(* Logix 5000 project; controller Electronic_Displays vendor 1 type 14 code 65 rev 17.4; software revision 17.01; part 4 of 9 *)
(* tags used below, declared in another part *)
   Address : STRING;   // "00" = all signs "01" = address 01 "02" = address 02 etc...(see protocol)
   CommandCode : STRING;   // "A" = text "B" = variable "C" = special "D" = text,norestart etc...(see protocol)
   FileLabel : STRING;   // "A" = default etc...(see protocol)
   ENText1Message : BOOL;   // 0 = don't sent message 1 = send message
   Text1Message : STRING;   // Actual Text Message to be Written to Screen (Line 1) 4 x 1 configuration
   ENText2Message : BOOL;   // 0 = don't sent message 1 = send message
   Text2Message : STRING;   // Actual Text Message to be Written to Screen (Line 2) 4 x 1 configuration
   ENText3Message : BOOL;   // 0 = don't sent message 1 = send message
   Text3Message : STRING;   // Actual Text Message to be Written to Screen (Line 3) 4 x 1 configuration
   ENText4Message : BOOL;   // 0 = don't sent message 1 = send message
   Text4Message : STRING;   // Actual Text Message to be Written to Screen (Line 4) 4 x 1 configuration
   ENTextFormats : BOOL;   // 0 = no additional text formatting 1 = enable text formatting
   TextFont : STRING;   // "0" = default "1" = SF7 "2" = SF10 "3" = SS16 "4" = SF16
   TextColor : STRING;   // "0" = Red (default) "1" = Green "2" = Yellow "3" = Rainbow1
   TextAlign : STRING;   // "M"=middle line "T"=top line "B"=bottom line "F"=fill (best for variables) "L"=left "R"=right
   TextAttribute : STRING;   // "0"=flashing off "1"=flashing on "2"=wide off "3"=wide on "4"=bold off "5"=bold on
   ENTextSpecials : BOOL;   // 0 = no additional text special formatting 1 = enable text special formatting
   TextEffect : STRING;   // "S"=scrolls "H"=hold "F"=flash "A"=slide up "B"=slide down "C"=slide left "D"=slide right "a"=roll up "b"=roll down "c"=
   TextSpeed : STRING;   // 1 - 8 "3" = Default (see protocol)
   TextPause : STRING;   // 00 - 99 "02" = Default (see protocol) [must be two digits] if not will not work!
   ENVariable1Message : BOOL;   // 0 = don't sent embedded variable 1 = send embedded variable
   Variable1Name : STRING;   // Name of variable Default is = U
   ENVariable2Message : BOOL;   // 0 = don't sent embedded variable 1 = send embedded variable
   Variable2Name : STRING;   // Name of variable Default is = V
   ENVariable3Message : BOOL;   // 0 = don't sent embedded variable 1 = send embedded variable
   Variable3Name : STRING;   // Name of variable Default is = W
   ENVariable4Message : BOOL;   // 0 = don't sent embedded variable 1 = send embedded variable
   Variable4Name : STRING;   // Name of variable Default is = X
   ENVariableFormats : BOOL;   // 0 = no additional text formatting 1 = enable text formatting
   VariableFont : STRING;   // "0" = default "1" = SF7 "2" = SF10 "3" = SS16 "4" = SF16 etc...(see protocol)
   VariableColor : STRING;   // "0" = Red (default) "1" = Green "2" = Yellow "3" = Rainbow1
   VariableAttribute : STRING;   // "0"=flashing off "1"=flashing on "2"=wide off "3"=wide on "4"=bold off "5"=bold on
   EN : BOOL;   // Instruction Interface Enable Bit
   DN : BOOL;   // Instruction Interface Done Bit
   IP : BOOL;   // Instruction Interface InProcess Bit
   ER : BOOL;   // Instruction Interface Error Bit
   Packet1Sent : STRING;   // The actual packet sent to the sign (Packet1)
   Packet2Sent : STRING;   // The actual packet sent to the sign (Packet2)
   Packet3Sent : STRING;   // The actual packet sent to the sign (Packet3)
   Packet4Sent : STRING;   // The actual packet sent to the sign (Packet4)
   Packet5Sent : STRING;   // The actual packet sent to the sign (Packet5)
   Packet6Sent : STRING;   // The actual packet sent to the sign (Packet6)
   SEQ : DINT;   // Sequence Number
   OktoCycle : BOOL;   // Ok to Cycle
   InCycle : BOOL;   // Incycle
   Error : BOOL;   // Error
   Enabled : BOOL;   // Enable ON Bit
   Done : BOOL;   // Done
   Disabled : BOOL;   // Disabled OFF Bit
   SignTextMessage1 : STRING;
   SignColor : STRING;
   SignFont : STRING;
   SignFileLabel : STRING;
   SignCommandCode : STRING;
   SignSOH : STRING;   // DO NOT EDIT = ^A
   SignAddress : STRING;
   SignSTX : STRING;   // DO NOT EDIT = ^B
   Packet : STRING[7];   // Packet Array to send to sign
   SignFontCommand : STRING;   // DO NOT EDIT = ^F
   SignColorCommand : STRING;   // DO NOT EDIT = ^O
   SignAlignCommand : STRING;   // DO NOT EDIT = ^G
   SignAlign : STRING;
   SignSpeedCommand : STRING;   // DO NOT EDIT = ^I
   SignSpeed : STRING;
   SignEffectCommand : STRING;   // DO NOT EDIT = ^E
   SignEffect : STRING;
   SignPauseCommand : STRING;   // DO NOT EDIT = ^J
   SignPause : STRING;
   SignTextMessage4 : STRING;
   SignTextMessage3 : STRING;
   SignTextMessage2 : STRING;
   SignNextLine : STRING;   // DO NOT EDIT = ^M
   SignNULL : STRING;
   SignVariableFont : STRING;
   SignVariableColor : STRING;
   SignVariable4 : STRING;
   SignVariable3 : STRING;
   SignVariable2 : STRING;
   SignVariable1 : STRING;
   SignVariableCommand : STRING;   // DO NOT EDIT = ^N
   Select : DINT;   // Packet Array Select
   TotalPacketCount : DINT[7];   // Total Character Count
   PacketMax : DINT;   // Max Packet Count
   SignMode2Command : STRING;   // DO NOT EDIT = H (make it hold)
   SignAttributeCommand : STRING;   // DO NOT EDIT = ^H
   SignAttribute : STRING;
   SignVariableAttribute : STRING;
   ENABLE : DINT;
(* SendSignMessage, continued *)

ROUTINE Logic   (* ladder *)
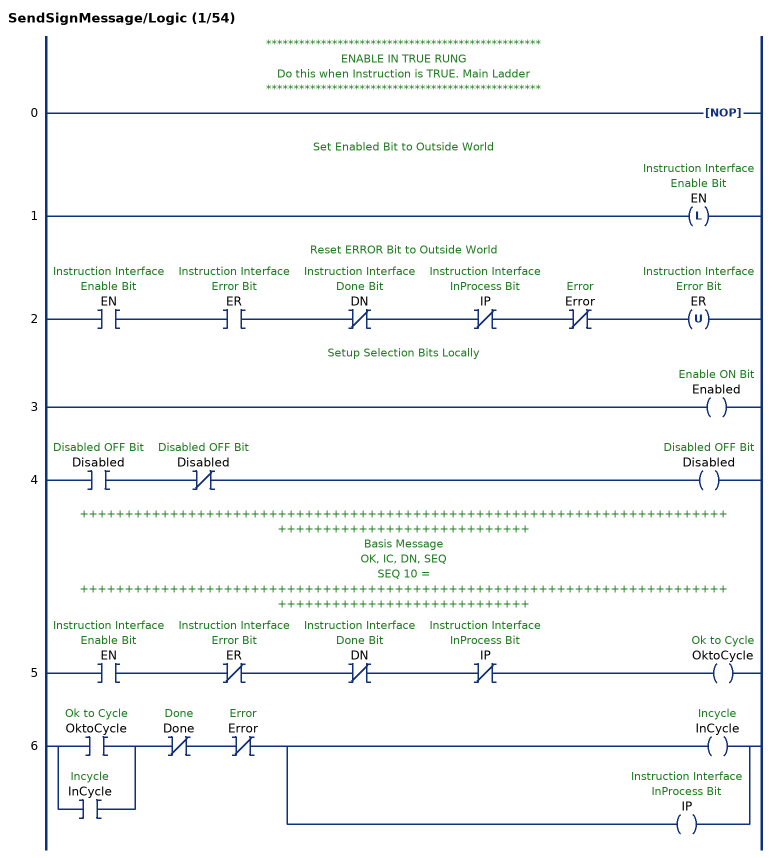
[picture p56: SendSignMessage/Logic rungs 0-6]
   // **************************************************
   // ENABLE IN TRUE RUNG
   // Do this when Instruction is TRUE. Main Ladder
   // **************************************************
   0: NOP();
   // Set Enabled Bit to Outside World
   1: OTL(EN);
   // Reset ERROR Bit to Outside World
   2: XIC(EN)XIC(ER)XIO(DN)XIO(IP)XIO(Error)OTU(ER);
   // Setup Selection Bits Locally
   3: OTE(Enabled);
   4: XIC(Disabled)XIO(Disabled)OTE(Disabled);
   // ++++++++++++++++++++++++++++++++++++++++++++++++++++++++++++++++++++++++++++++++++++++++++++++++++++
   // Basis Message
   // OK, IC, DN, SEQ
   // SEQ 10 =
   // ++++++++++++++++++++++++++++++++++++++++++++++++++++++++++++++++++++++++++++++++++++++++++++++++++++
   5: XIC(EN)XIO(ER)XIO(DN)XIO(IP)OTE(OktoCycle);
   6: [XIC(OktoCycle) ,XIC(InCycle) ]XIO(Done)XIO(Error)[OTE(InCycle) ,OTE(IP) ];
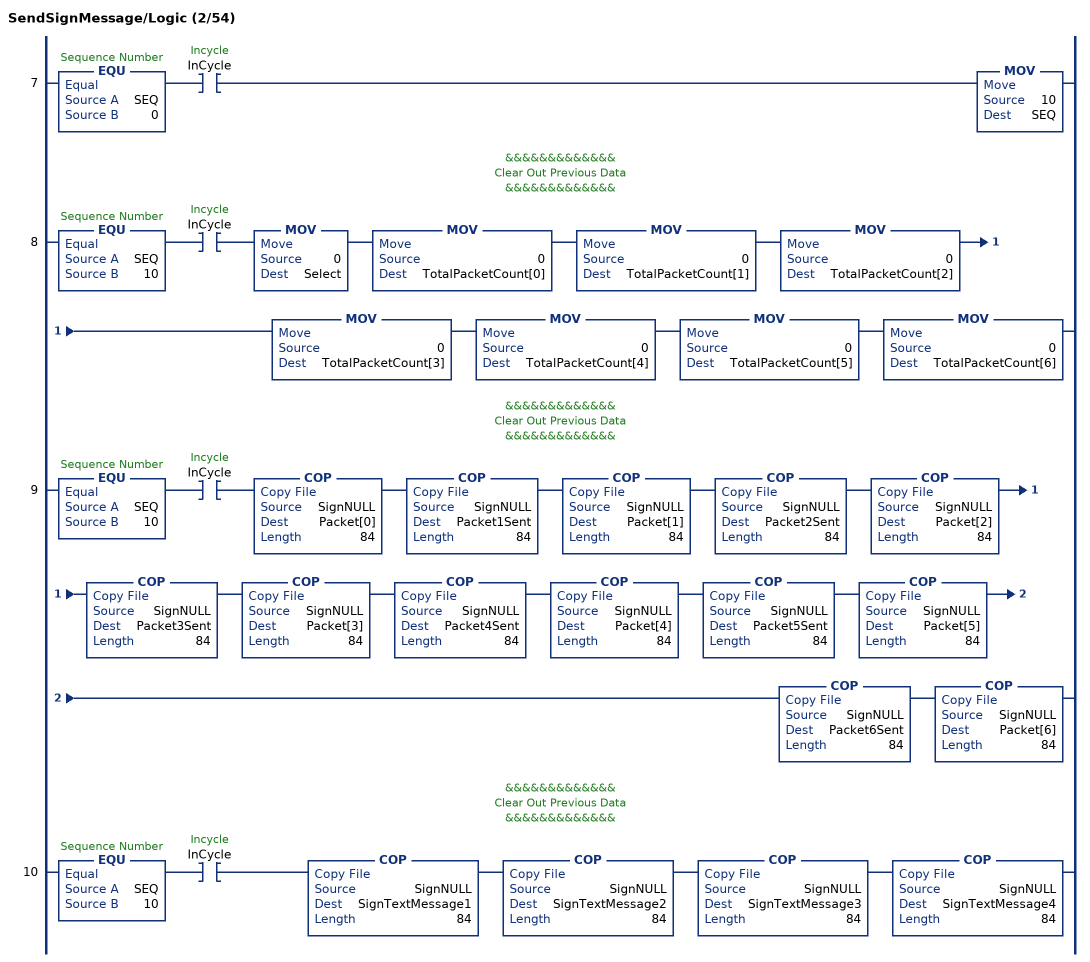
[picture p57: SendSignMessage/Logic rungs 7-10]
   7: EQU(SEQ,0)XIC(InCycle)MOV(10,SEQ);
   // &&&&&&&&&&&&&
   // Clear Out Previous Data
   // &&&&&&&&&&&&&
   8: EQU(SEQ,10)XIC(InCycle)MOV(0,Select)MOV(0,TotalPacketCount[0])MOV(0,TotalPacketCount[1])MOV(0,TotalPacketCount[2])MOV(0,TotalPacketCount[3])MOV(0,TotalPacketCount[4])MOV(0,TotalPacketCount[5])MOV(0,TotalPacketCount[6]);
   // &&&&&&&&&&&&&
   // Clear Out Previous Data
   // &&&&&&&&&&&&&
   9: EQU(SEQ,10)XIC(InCycle)COP(SignNULL,Packet[0],84)COP(SignNULL,Packet1Sent,84)COP(SignNULL,Packet[1],84)COP(SignNULL,Packet2Sent,84)COP(SignNULL,Packet[2],84)COP(SignNULL,Packet3Sent,84)COP(SignNULL,Packet[3],84)COP(SignNULL,Packet4Sent,84)COP(SignNULL,Packet[4],84)COP(SignNULL,Packet5Sent,84)COP(SignNULL,Packet[5],84)COP(SignNULL,Packet6Sent,84)COP(SignNULL,Packet[6],84);
   // &&&&&&&&&&&&&
   // Clear Out Previous Data
   // &&&&&&&&&&&&&
   10: EQU(SEQ,10)XIC(InCycle)COP(SignNULL,SignTextMessage1,84)COP(SignNULL,SignTextMessage2,84)COP(SignNULL,SignTextMessage3,84)COP(SignNULL,SignTextMessage4,84);
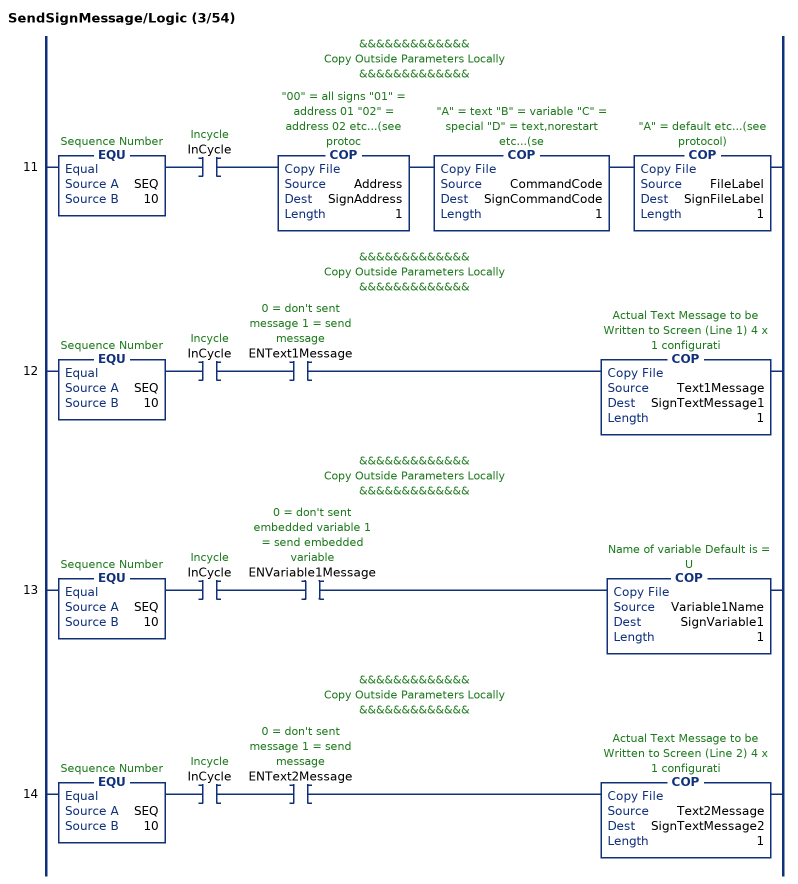
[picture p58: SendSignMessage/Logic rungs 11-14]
   // &&&&&&&&&&&&&
   // Copy Outside Parameters Locally
   // &&&&&&&&&&&&&
   11: EQU(SEQ,10)XIC(InCycle)COP(Address,SignAddress,1)COP(CommandCode,SignCommandCode,1)COP(FileLabel,SignFileLabel,1);
   // &&&&&&&&&&&&&
   // Copy Outside Parameters Locally
   // &&&&&&&&&&&&&
   12: EQU(SEQ,10)XIC(InCycle)XIC(ENText1Message)COP(Text1Message,SignTextMessage1,1);
   // &&&&&&&&&&&&&
   // Copy Outside Parameters Locally
   // &&&&&&&&&&&&&
   13: EQU(SEQ,10)XIC(InCycle)XIC(ENVariable1Message)COP(Variable1Name,SignVariable1,1);
   // &&&&&&&&&&&&&
   // Copy Outside Parameters Locally
   // &&&&&&&&&&&&&
   14: EQU(SEQ,10)XIC(InCycle)XIC(ENText2Message)COP(Text2Message,SignTextMessage2,1);
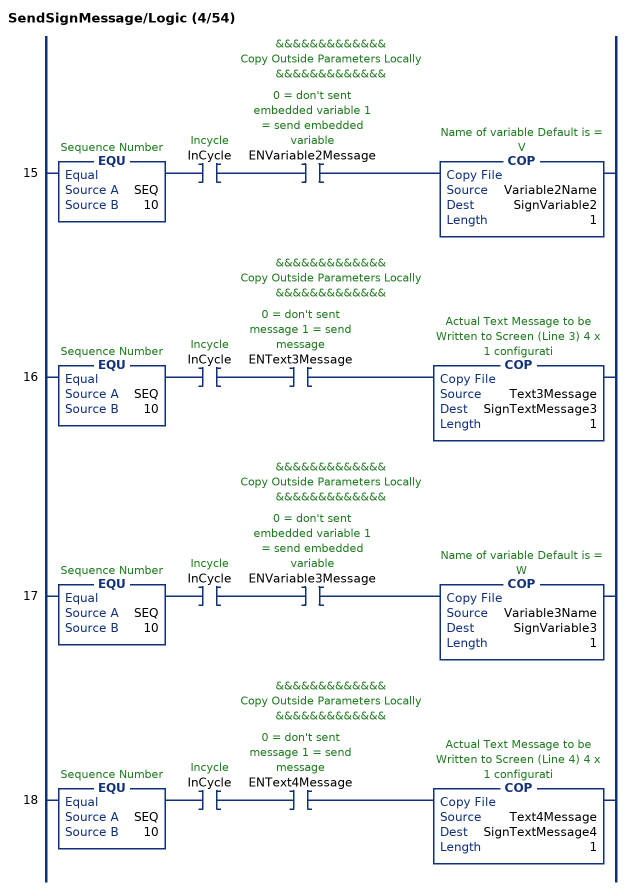
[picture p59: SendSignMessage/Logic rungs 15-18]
   // &&&&&&&&&&&&&
   // Copy Outside Parameters Locally
   // &&&&&&&&&&&&&
   15: EQU(SEQ,10)XIC(InCycle)XIC(ENVariable2Message)COP(Variable2Name,SignVariable2,1);
   // &&&&&&&&&&&&&
   // Copy Outside Parameters Locally
   // &&&&&&&&&&&&&
   16: EQU(SEQ,10)XIC(InCycle)XIC(ENText3Message)COP(Text3Message,SignTextMessage3,1);
   // &&&&&&&&&&&&&
   // Copy Outside Parameters Locally
   // &&&&&&&&&&&&&
   17: EQU(SEQ,10)XIC(InCycle)XIC(ENVariable3Message)COP(Variable3Name,SignVariable3,1);
   // &&&&&&&&&&&&&
   // Copy Outside Parameters Locally
   // &&&&&&&&&&&&&
   18: EQU(SEQ,10)XIC(InCycle)XIC(ENText4Message)COP(Text4Message,SignTextMessage4,1);
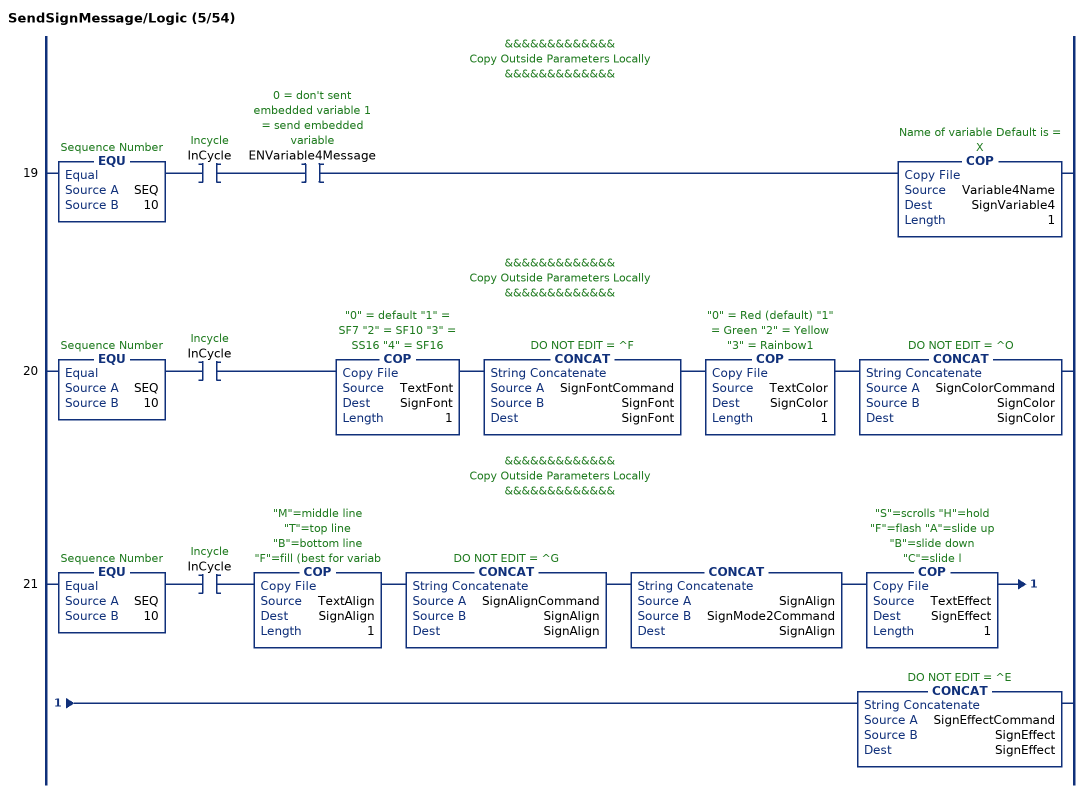
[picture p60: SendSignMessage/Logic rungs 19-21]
   // &&&&&&&&&&&&&
   // Copy Outside Parameters Locally
   // &&&&&&&&&&&&&
   19: EQU(SEQ,10)XIC(InCycle)XIC(ENVariable4Message)COP(Variable4Name,SignVariable4,1);
   // &&&&&&&&&&&&&
   // Copy Outside Parameters Locally
   // &&&&&&&&&&&&&
   20: EQU(SEQ,10)XIC(InCycle)COP(TextFont,SignFont,1)CONCAT(SignFontCommand,SignFont,SignFont)COP(TextColor,SignColor,1)CONCAT(SignColorCommand,SignColor,SignColor);
   // &&&&&&&&&&&&&
   // Copy Outside Parameters Locally
   // &&&&&&&&&&&&&
   21: EQU(SEQ,10)XIC(InCycle)COP(TextAlign,SignAlign,1)CONCAT(SignAlignCommand,SignAlign,SignAlign)CONCAT(SignAlign,SignMode2Command,SignAlign)COP(TextEffect,SignEffect,1)CONCAT(SignEffectCommand,SignEffect,SignEffect);
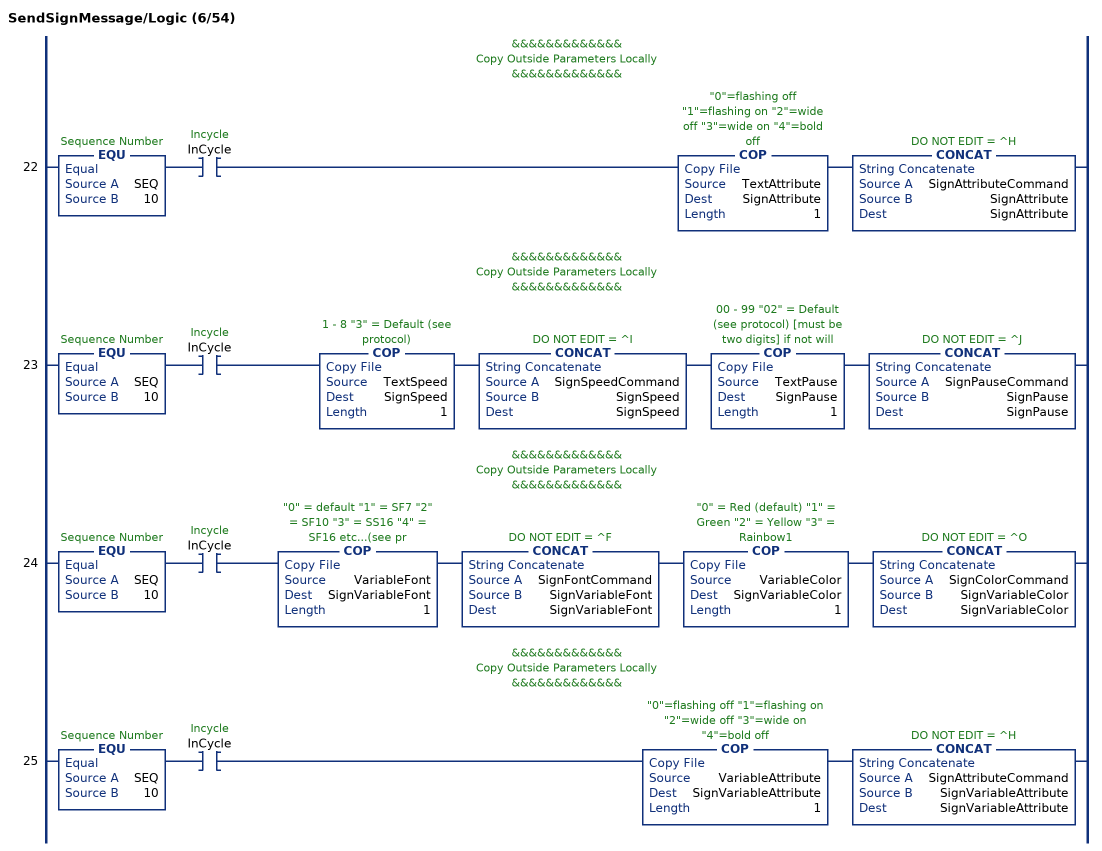
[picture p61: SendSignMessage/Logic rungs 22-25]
   // &&&&&&&&&&&&&
   // Copy Outside Parameters Locally
   // &&&&&&&&&&&&&
   22: EQU(SEQ,10)XIC(InCycle)COP(TextAttribute,SignAttribute,1)CONCAT(SignAttributeCommand,SignAttribute,SignAttribute);
   // &&&&&&&&&&&&&
   // Copy Outside Parameters Locally
   // &&&&&&&&&&&&&
   23: EQU(SEQ,10)XIC(InCycle)COP(TextSpeed,SignSpeed,1)CONCAT(SignSpeedCommand,SignSpeed,SignSpeed)COP(TextPause,SignPause,1)CONCAT(SignPauseCommand,SignPause,SignPause);
   // &&&&&&&&&&&&&
   // Copy Outside Parameters Locally
   // &&&&&&&&&&&&&
   24: EQU(SEQ,10)XIC(InCycle)COP(VariableFont,SignVariableFont,1)CONCAT(SignFontCommand,SignVariableFont,SignVariableFont)COP(VariableColor,SignVariableColor,1)CONCAT(SignColorCommand,SignVariableColor,SignVariableColor);
   // &&&&&&&&&&&&&
   // Copy Outside Parameters Locally
   // &&&&&&&&&&&&&
   25: EQU(SEQ,10)XIC(InCycle)COP(VariableAttribute,SignVariableAttribute,1)CONCAT(SignAttributeCommand,SignVariableAttribute,SignVariableAttribute);
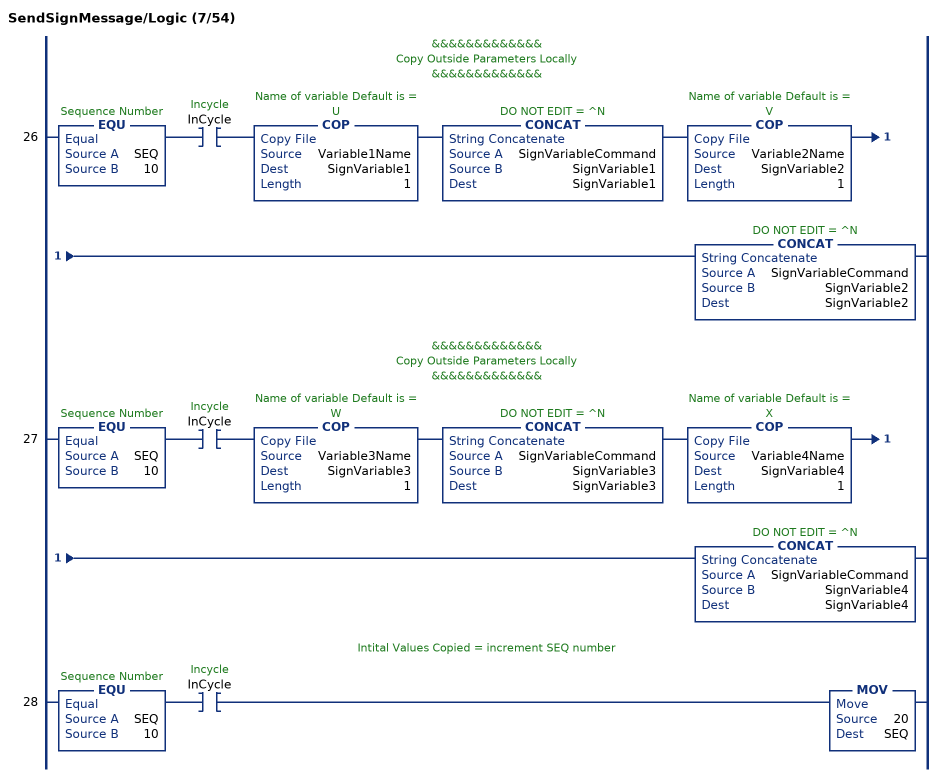
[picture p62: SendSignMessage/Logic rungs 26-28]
   // &&&&&&&&&&&&&
   // Copy Outside Parameters Locally
   // &&&&&&&&&&&&&
   26: EQU(SEQ,10)XIC(InCycle)COP(Variable1Name,SignVariable1,1)CONCAT(SignVariableCommand,SignVariable1,SignVariable1)COP(Variable2Name,SignVariable2,1)CONCAT(SignVariableCommand,SignVariable2,SignVariable2);
   // &&&&&&&&&&&&&
   // Copy Outside Parameters Locally
   // &&&&&&&&&&&&&
   27: EQU(SEQ,10)XIC(InCycle)COP(Variable3Name,SignVariable3,1)CONCAT(SignVariableCommand,SignVariable3,SignVariable3)COP(Variable4Name,SignVariable4,1)CONCAT(SignVariableCommand,SignVariable4,SignVariable4);
   // Intital Values Copied = increment SEQ number
   28: EQU(SEQ,10)XIC(InCycle)MOV(20,SEQ);
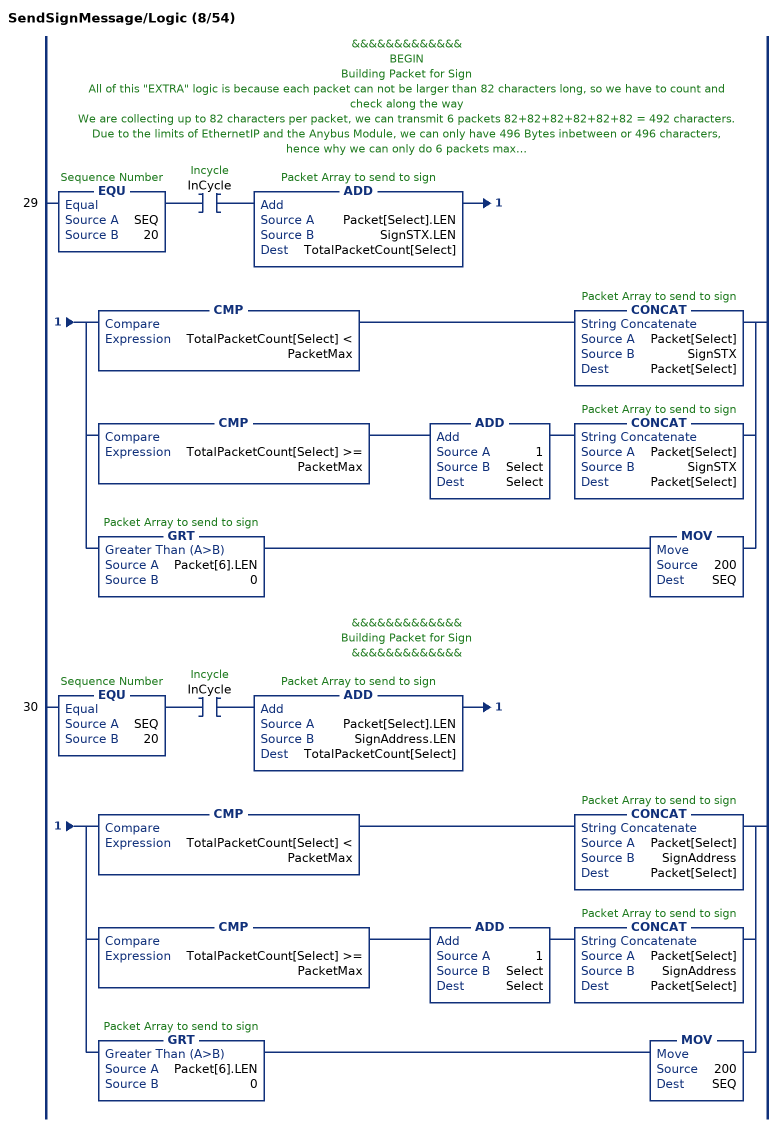
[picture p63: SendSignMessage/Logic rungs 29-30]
   // &&&&&&&&&&&&&
   // BEGIN
   // Building Packet for Sign
   // All of this "EXTRA" logic is because each packet can not be larger than 82 characters long, so we have to count and check along the way
   // We are collecting up to 82 characters per packet, we can transmit 6 packets 82+82+82+82+82+82 = 492 characters.
   // Due to the limits of EthernetIP and the Anybus Module, we can only have 496 Bytes inbetween or 496 characters, hence why we can only do 6 packets max.
   // Once we exceed this, we will fault and ERROR trap any windy typing people.
   // &&&&&&&&&&&&&
   29: EQU(SEQ,20)XIC(InCycle)ADD(Packet[Select].LEN,SignSTX.LEN,TotalPacketCount[Select])[CMP(TotalPacketCount[Select] < PacketMax) CONCAT(Packet[Select],SignSTX,Packet[Select]) ,CMP(TotalPacketCount[Select] >= PacketMax) ADD(1,Select,Select) CONCAT(Packet[Select],SignSTX,Packet[Select]) ,GRT(Packet[6].LEN,0) MOV(200,SEQ) ];
   // &&&&&&&&&&&&&
   // Building Packet for Sign
   // &&&&&&&&&&&&&
   30: EQU(SEQ,20)XIC(InCycle)ADD(Packet[Select].LEN,SignAddress.LEN,TotalPacketCount[Select])[CMP(TotalPacketCount[Select] < PacketMax) CONCAT(Packet[Select],SignAddress,Packet[Select]) ,CMP(TotalPacketCount[Select] >= PacketMax) ADD(1,Select,Select) CONCAT(Packet[Select],SignAddress,Packet[Select]) ,GRT(Packet[6].LEN,0) MOV(200,SEQ) ];
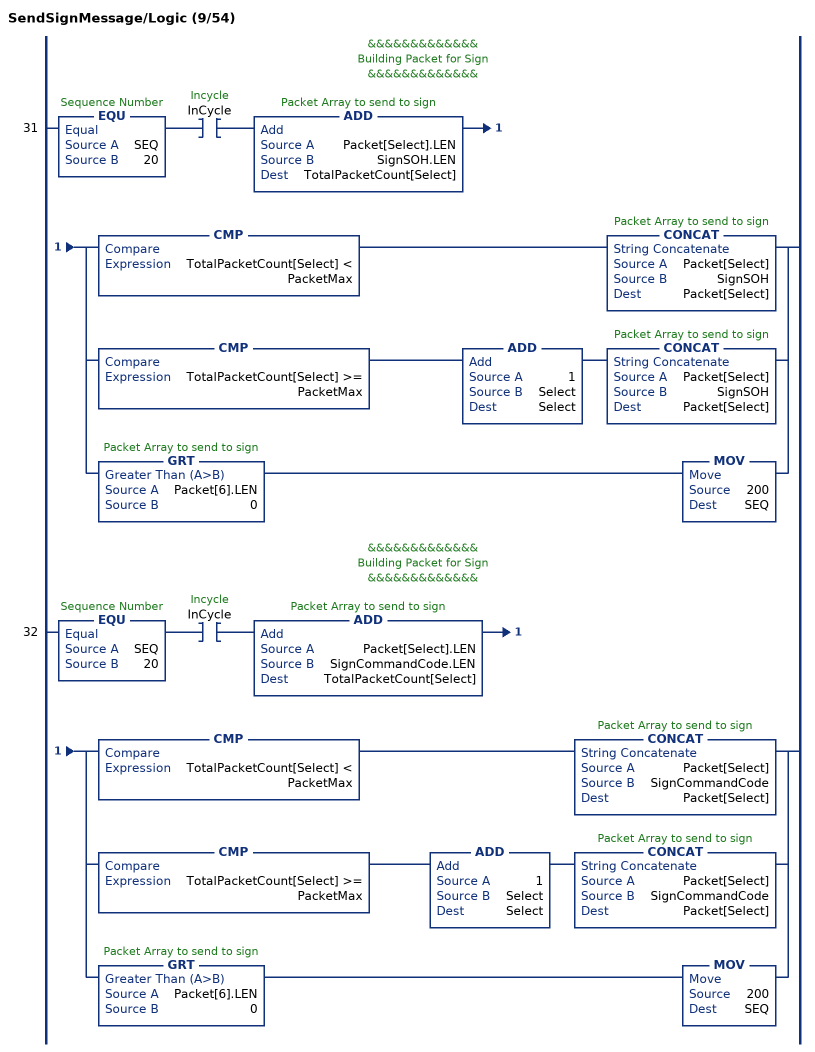
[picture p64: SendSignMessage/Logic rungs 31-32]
   // &&&&&&&&&&&&&
   // Building Packet for Sign
   // &&&&&&&&&&&&&
   31: EQU(SEQ,20)XIC(InCycle)ADD(Packet[Select].LEN,SignSOH.LEN,TotalPacketCount[Select])[CMP(TotalPacketCount[Select] < PacketMax) CONCAT(Packet[Select],SignSOH,Packet[Select]) ,CMP(TotalPacketCount[Select] >= PacketMax) ADD(1,Select,Select) CONCAT(Packet[Select],SignSOH,Packet[Select]) ,GRT(Packet[6].LEN,0) MOV(200,SEQ) ];
   // &&&&&&&&&&&&&
   // Building Packet for Sign
   // &&&&&&&&&&&&&
   32: EQU(SEQ,20)XIC(InCycle)ADD(Packet[Select].LEN,SignCommandCode.LEN,TotalPacketCount[Select])[CMP(TotalPacketCount[Select] < PacketMax) CONCAT(Packet[Select],SignCommandCode,Packet[Select]) ,CMP(TotalPacketCount[Select] >= PacketMax) ADD(1,Select,Select) CONCAT(Packet[Select],SignCommandCode,Packet[Select]) ,GRT(Packet[6].LEN,0) MOV(200,SEQ) ];
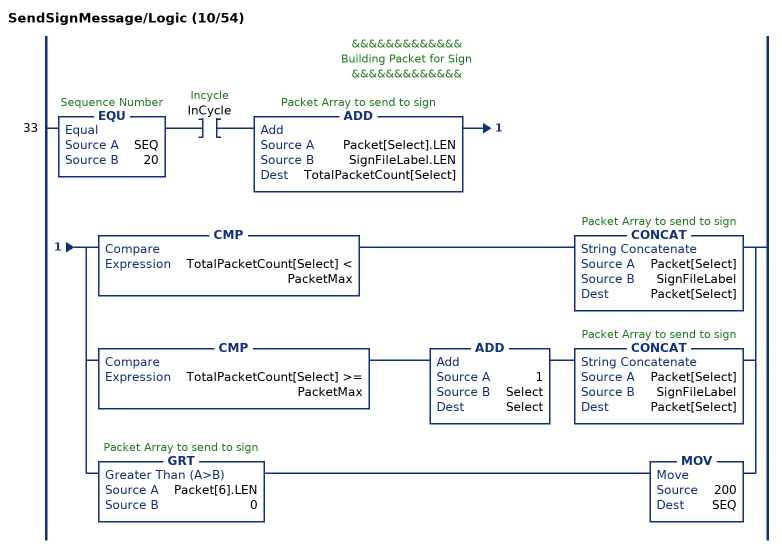
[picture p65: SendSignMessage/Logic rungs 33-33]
   // &&&&&&&&&&&&&
   // Building Packet for Sign
   // &&&&&&&&&&&&&
   33: EQU(SEQ,20)XIC(InCycle)ADD(Packet[Select].LEN,SignFileLabel.LEN,TotalPacketCount[Select])[CMP(TotalPacketCount[Select] < PacketMax) CONCAT(Packet[Select],SignFileLabel,Packet[Select]) ,CMP(TotalPacketCount[Select] >= PacketMax) ADD(1,Select,Select) CONCAT(Packet[Select],SignFileLabel,Packet[Select]) ,GRT(Packet[6].LEN,0) MOV(200,SEQ) ];
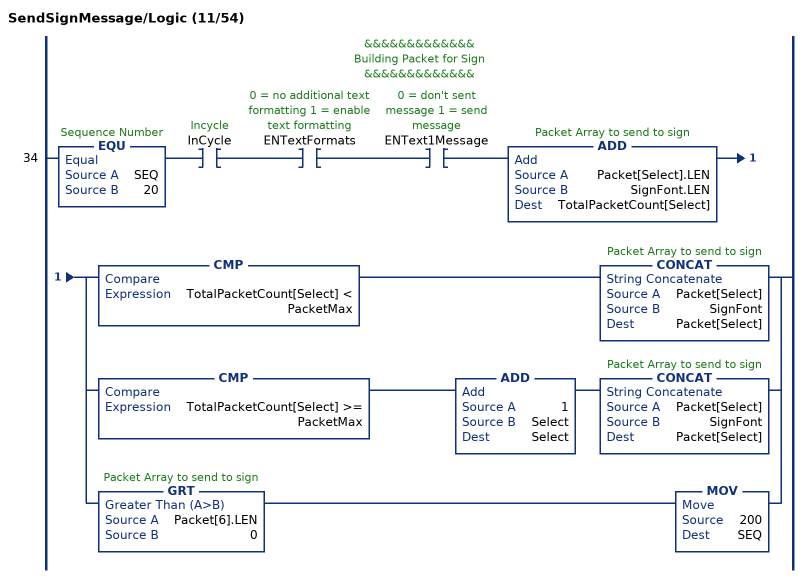
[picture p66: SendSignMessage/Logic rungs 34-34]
   // &&&&&&&&&&&&&
   // Building Packet for Sign
   // &&&&&&&&&&&&&
   34: EQU(SEQ,20)XIC(InCycle)XIC(ENTextFormats)XIC(ENText1Message)ADD(Packet[Select].LEN,SignFont.LEN,TotalPacketCount[Select])[CMP(TotalPacketCount[Select] < PacketMax) CONCAT(Packet[Select],SignFont,Packet[Select]) ,CMP(TotalPacketCount[Select] >= PacketMax) ADD(1,Select,Select) CONCAT(Packet[Select],SignFont,Packet[Select]) ,GRT(Packet[6].LEN,0) MOV(200,SEQ) ];
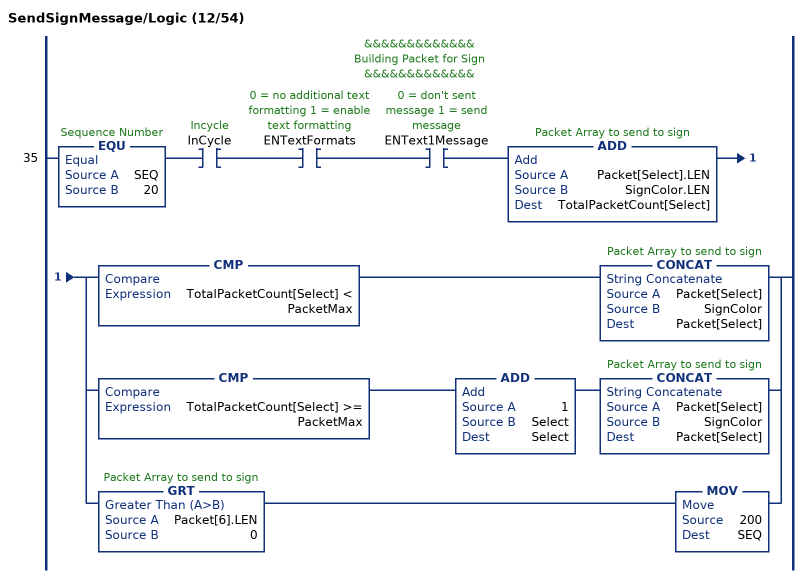
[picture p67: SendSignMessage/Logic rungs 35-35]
   // &&&&&&&&&&&&&
   // Building Packet for Sign
   // &&&&&&&&&&&&&
   35: EQU(SEQ,20)XIC(InCycle)XIC(ENTextFormats)XIC(ENText1Message)ADD(Packet[Select].LEN,SignColor.LEN,TotalPacketCount[Select])[CMP(TotalPacketCount[Select] < PacketMax) CONCAT(Packet[Select],SignColor,Packet[Select]) ,CMP(TotalPacketCount[Select] >= PacketMax) ADD(1,Select,Select) CONCAT(Packet[Select],SignColor,Packet[Select]) ,GRT(Packet[6].LEN,0) MOV(200,SEQ) ];
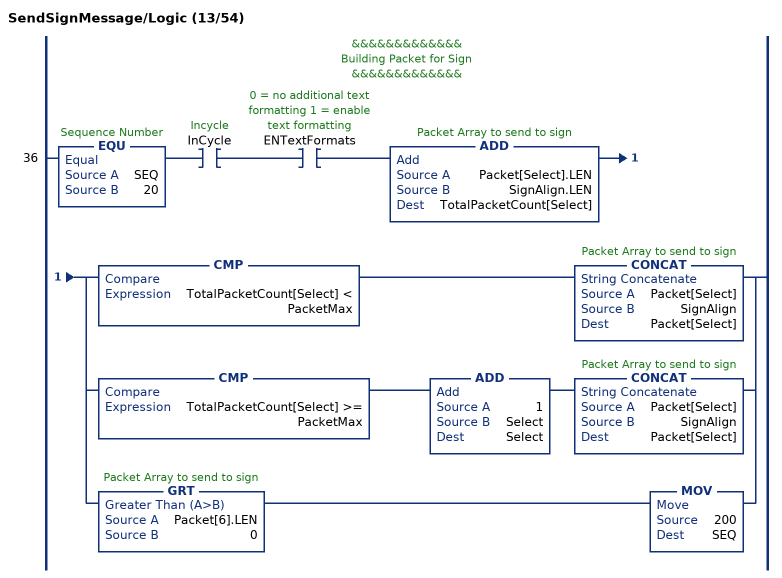
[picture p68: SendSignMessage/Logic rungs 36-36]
   // &&&&&&&&&&&&&
   // Building Packet for Sign
   // &&&&&&&&&&&&&
   36: EQU(SEQ,20)XIC(InCycle)XIC(ENTextFormats)ADD(Packet[Select].LEN,SignAlign.LEN,TotalPacketCount[Select])[CMP(TotalPacketCount[Select] < PacketMax) CONCAT(Packet[Select],SignAlign,Packet[Select]) ,CMP(TotalPacketCount[Select] >= PacketMax) ADD(1,Select,Select) CONCAT(Packet[Select],SignAlign,Packet[Select]) ,GRT(Packet[6].LEN,0) MOV(200,SEQ) ];
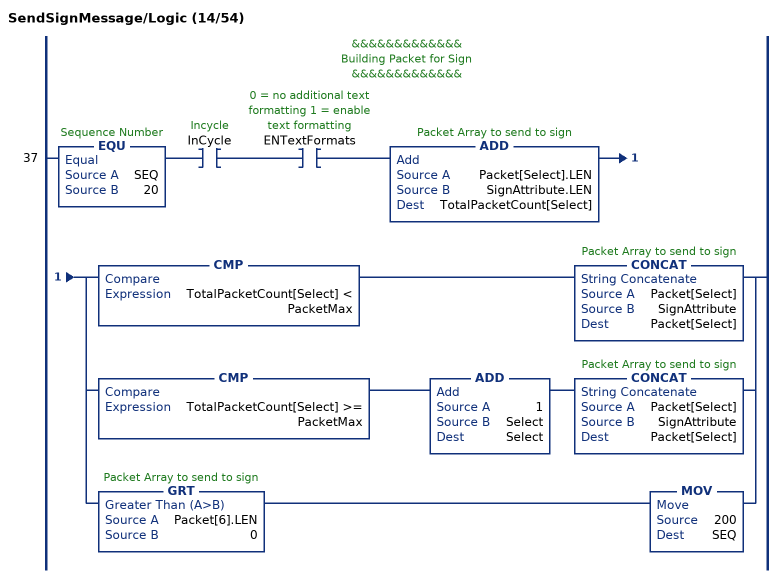
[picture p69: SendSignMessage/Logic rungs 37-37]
   // &&&&&&&&&&&&&
   // Building Packet for Sign
   // &&&&&&&&&&&&&
   37: EQU(SEQ,20)XIC(InCycle)XIC(ENTextFormats)ADD(Packet[Select].LEN,SignAttribute.LEN,TotalPacketCount[Select])[CMP(TotalPacketCount[Select] < PacketMax) CONCAT(Packet[Select],SignAttribute,Packet[Select]) ,CMP(TotalPacketCount[Select] >= PacketMax) ADD(1,Select,Select) CONCAT(Packet[Select],SignAttribute,Packet[Select]) ,GRT(Packet[6].LEN,0) MOV(200,SEQ) ];
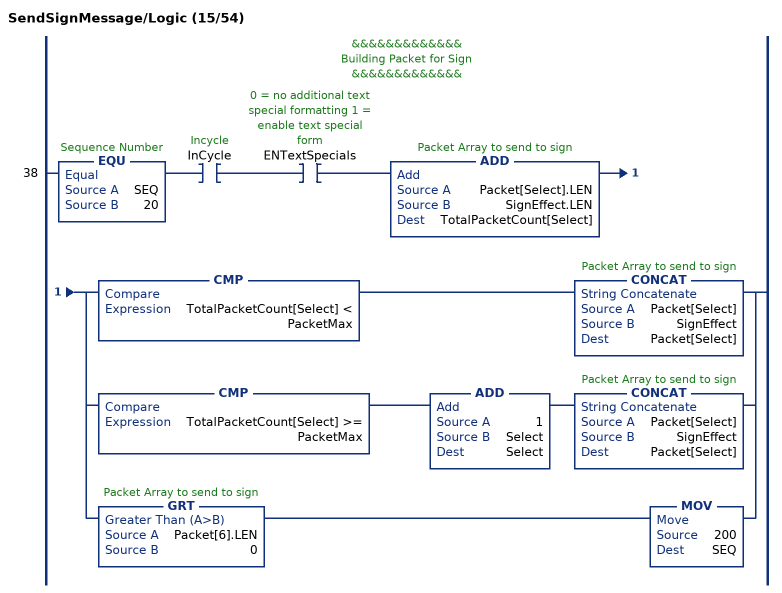
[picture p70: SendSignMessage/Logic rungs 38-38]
   // &&&&&&&&&&&&&
   // Building Packet for Sign
   // &&&&&&&&&&&&&
   38: EQU(SEQ,20)XIC(InCycle)XIC(ENTextSpecials)ADD(Packet[Select].LEN,SignEffect.LEN,TotalPacketCount[Select])[CMP(TotalPacketCount[Select] < PacketMax) CONCAT(Packet[Select],SignEffect,Packet[Select]) ,CMP(TotalPacketCount[Select] >= PacketMax) ADD(1,Select,Select) CONCAT(Packet[Select],SignEffect,Packet[Select]) ,GRT(Packet[6].LEN,0) MOV(200,SEQ) ];
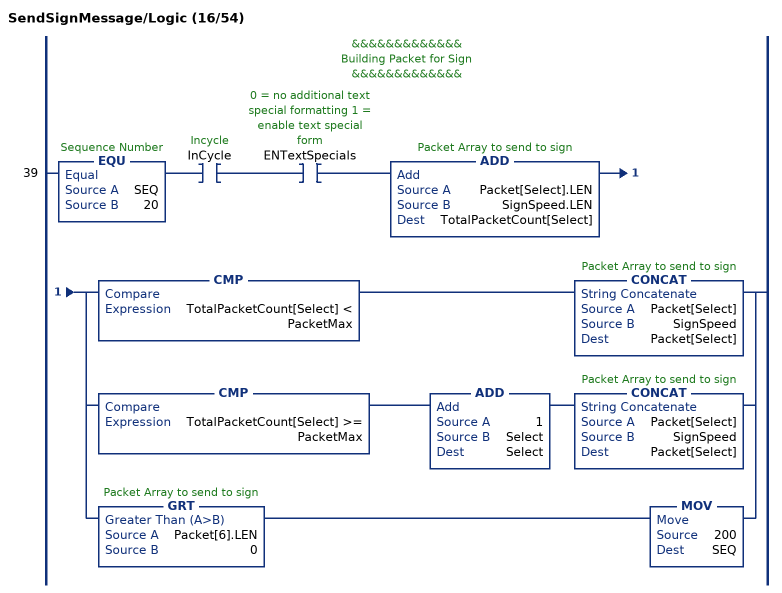
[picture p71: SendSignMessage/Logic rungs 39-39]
   // &&&&&&&&&&&&&
   // Building Packet for Sign
   // &&&&&&&&&&&&&
   39: EQU(SEQ,20)XIC(InCycle)XIC(ENTextSpecials)ADD(Packet[Select].LEN,SignSpeed.LEN,TotalPacketCount[Select])[CMP(TotalPacketCount[Select] < PacketMax) CONCAT(Packet[Select],SignSpeed,Packet[Select]) ,CMP(TotalPacketCount[Select] >= PacketMax) ADD(1,Select,Select) CONCAT(Packet[Select],SignSpeed,Packet[Select]) ,GRT(Packet[6].LEN,0) MOV(200,SEQ) ];
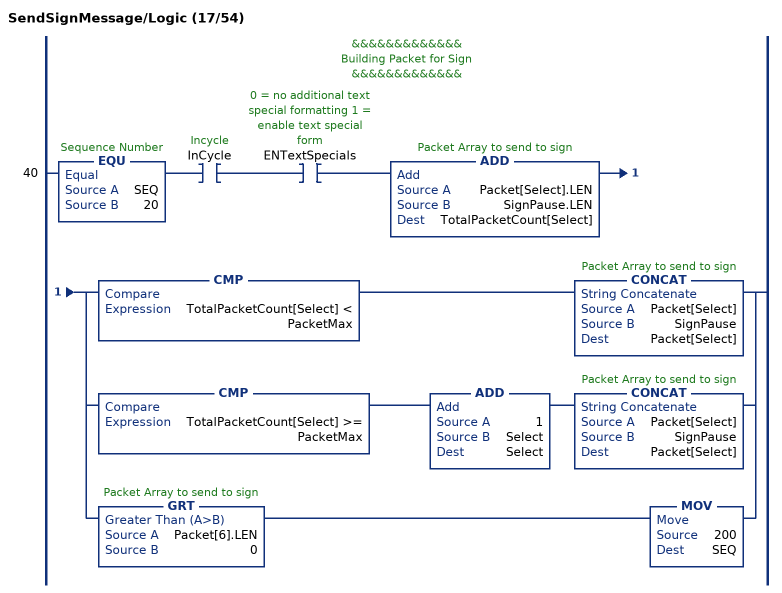
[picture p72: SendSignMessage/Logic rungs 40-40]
   // &&&&&&&&&&&&&
   // Building Packet for Sign
   // &&&&&&&&&&&&&
   40: EQU(SEQ,20)XIC(InCycle)XIC(ENTextSpecials)ADD(Packet[Select].LEN,SignPause.LEN,TotalPacketCount[Select])[CMP(TotalPacketCount[Select] < PacketMax) CONCAT(Packet[Select],SignPause,Packet[Select]) ,CMP(TotalPacketCount[Select] >= PacketMax) ADD(1,Select,Select) CONCAT(Packet[Select],SignPause,Packet[Select]) ,GRT(Packet[6].LEN,0) MOV(200,SEQ) ];
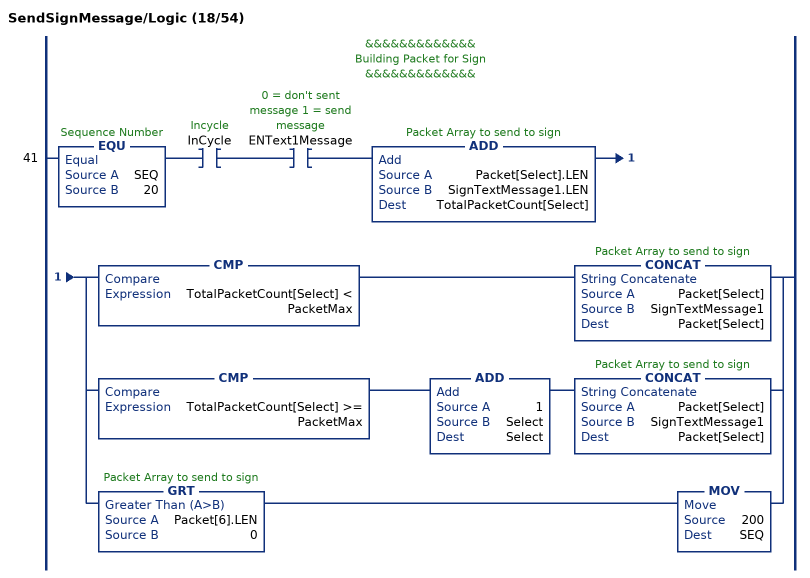
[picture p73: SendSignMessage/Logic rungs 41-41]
   // &&&&&&&&&&&&&
   // Building Packet for Sign
   // &&&&&&&&&&&&&
   41: EQU(SEQ,20)XIC(InCycle)XIC(ENText1Message)ADD(Packet[Select].LEN,SignTextMessage1.LEN,TotalPacketCount[Select])[CMP(TotalPacketCount[Select] < PacketMax) CONCAT(Packet[Select],SignTextMessage1,Packet[Select]) ,CMP(TotalPacketCount[Select] >= PacketMax) ADD(1,Select,Select) CONCAT(Packet[Select],SignTextMessage1,Packet[Select]) ,GRT(Packet[6].LEN,0) MOV(200,SEQ) ];
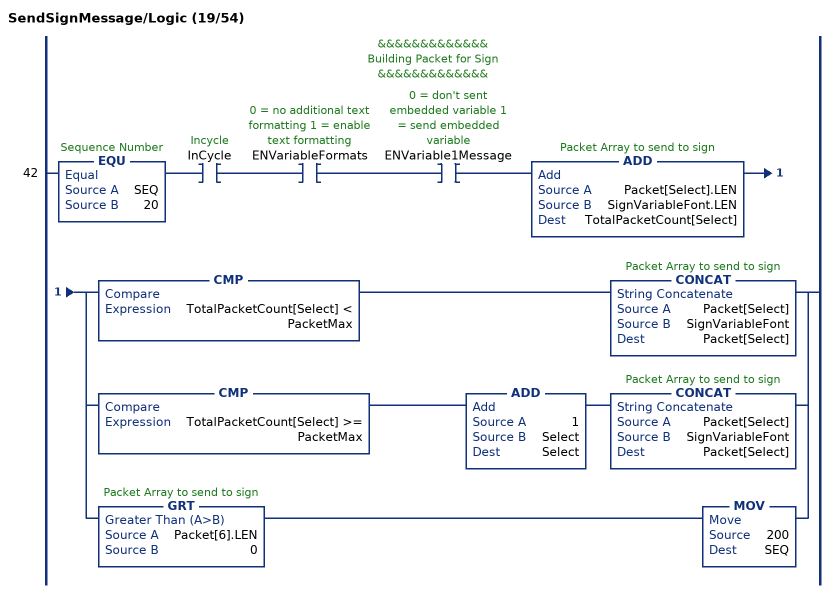
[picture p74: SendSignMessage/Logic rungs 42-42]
   // &&&&&&&&&&&&&
   // Building Packet for Sign
   // &&&&&&&&&&&&&
   42: EQU(SEQ,20)XIC(InCycle)XIC(ENVariableFormats)XIC(ENVariable1Message)ADD(Packet[Select].LEN,SignVariableFont.LEN,TotalPacketCount[Select])[CMP(TotalPacketCount[Select] < PacketMax) CONCAT(Packet[Select],SignVariableFont,Packet[Select]) ,CMP(TotalPacketCount[Select] >= PacketMax) ADD(1,Select,Select) CONCAT(Packet[Select],SignVariableFont,Packet[Select]) ,GRT(Packet[6].LEN,0) MOV(200,SEQ) ];
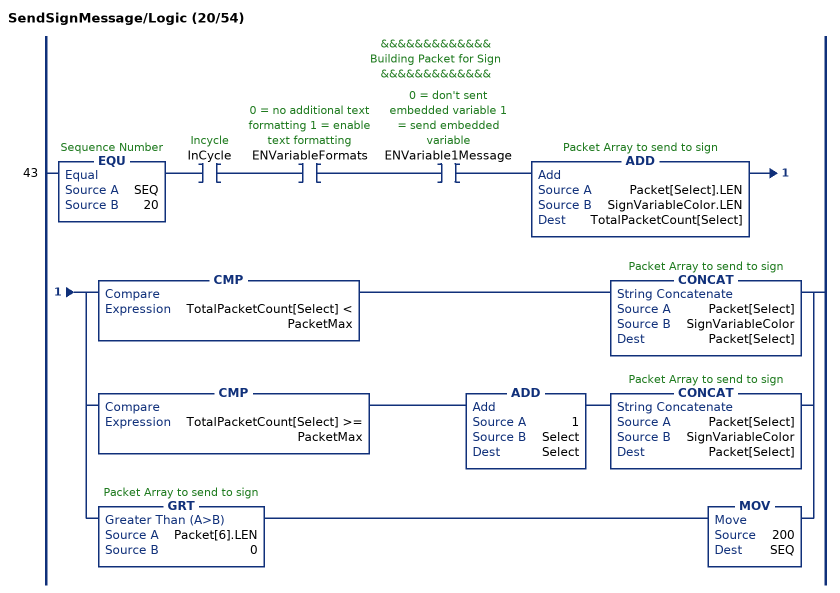
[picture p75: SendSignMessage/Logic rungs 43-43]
   // &&&&&&&&&&&&&
   // Building Packet for Sign
   // &&&&&&&&&&&&&
   43: EQU(SEQ,20)XIC(InCycle)XIC(ENVariableFormats)XIC(ENVariable1Message)ADD(Packet[Select].LEN,SignVariableColor.LEN,TotalPacketCount[Select])[CMP(TotalPacketCount[Select] < PacketMax) CONCAT(Packet[Select],SignVariableColor,Packet[Select]) ,CMP(TotalPacketCount[Select] >= PacketMax) ADD(1,Select,Select) CONCAT(Packet[Select],SignVariableColor,Packet[Select]) ,GRT(Packet[6].LEN,0) MOV(200,SEQ) ];
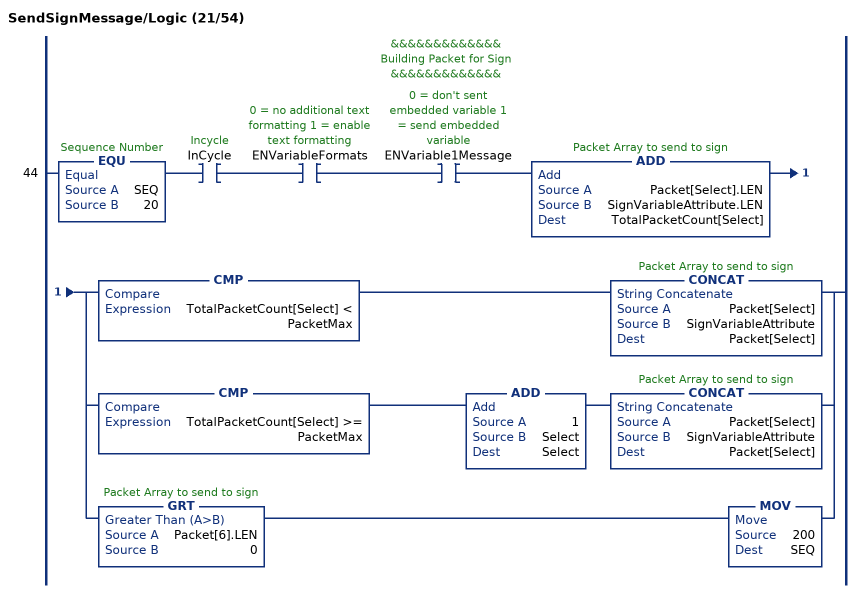
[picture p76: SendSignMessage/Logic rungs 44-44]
   // &&&&&&&&&&&&&
   // Building Packet for Sign
   // &&&&&&&&&&&&&
   44: EQU(SEQ,20)XIC(InCycle)XIC(ENVariableFormats)XIC(ENVariable1Message)ADD(Packet[Select].LEN,SignVariableAttribute.LEN,TotalPacketCount[Select])[CMP(TotalPacketCount[Select] < PacketMax) CONCAT(Packet[Select],SignVariableAttribute,Packet[Select]) ,CMP(TotalPacketCount[Select] >= PacketMax) ADD(1,Select,Select) CONCAT(Packet[Select],SignVariableAttribute,Packet[Select]) ,GRT(Packet[6].LEN,0) MOV(200,SEQ) ];
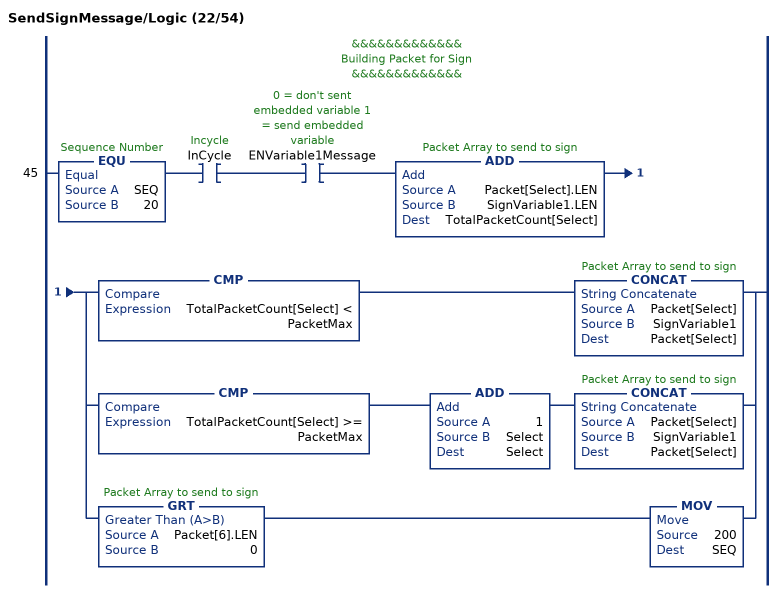
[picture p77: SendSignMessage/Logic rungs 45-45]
   // &&&&&&&&&&&&&
   // Building Packet for Sign
   // &&&&&&&&&&&&&
   45: EQU(SEQ,20)XIC(InCycle)XIC(ENVariable1Message)ADD(Packet[Select].LEN,SignVariable1.LEN,TotalPacketCount[Select])[CMP(TotalPacketCount[Select] < PacketMax) CONCAT(Packet[Select],SignVariable1,Packet[Select]) ,CMP(TotalPacketCount[Select] >= PacketMax) ADD(1,Select,Select) CONCAT(Packet[Select],SignVariable1,Packet[Select]) ,GRT(Packet[6].LEN,0) MOV(200,SEQ) ];
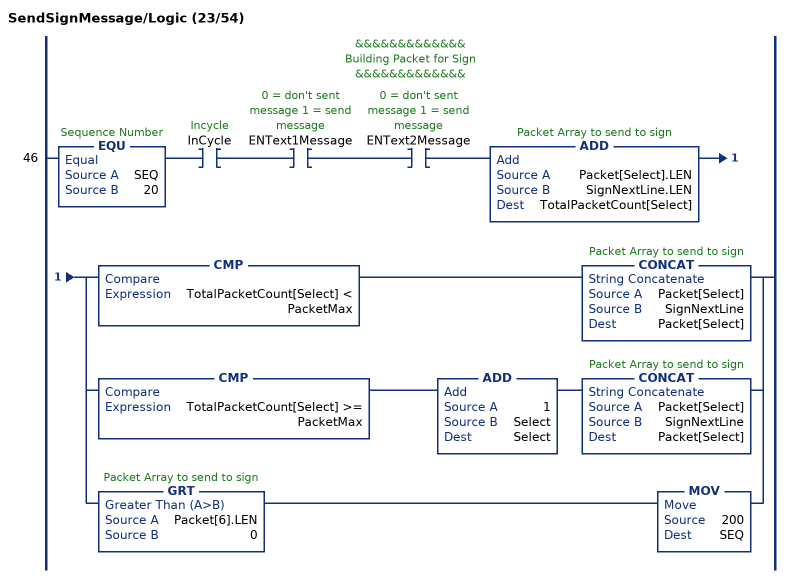
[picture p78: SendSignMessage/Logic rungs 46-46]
   // &&&&&&&&&&&&&
   // Building Packet for Sign
   // &&&&&&&&&&&&&
   46: EQU(SEQ,20)XIC(InCycle)XIC(ENText1Message)XIC(ENText2Message)ADD(Packet[Select].LEN,SignNextLine.LEN,TotalPacketCount[Select])[CMP(TotalPacketCount[Select] < PacketMax) CONCAT(Packet[Select],SignNextLine,Packet[Select]) ,CMP(TotalPacketCount[Select] >= PacketMax) ADD(1,Select,Select) CONCAT(Packet[Select],SignNextLine,Packet[Select]) ,GRT(Packet[6].LEN,0) MOV(200,SEQ) ];
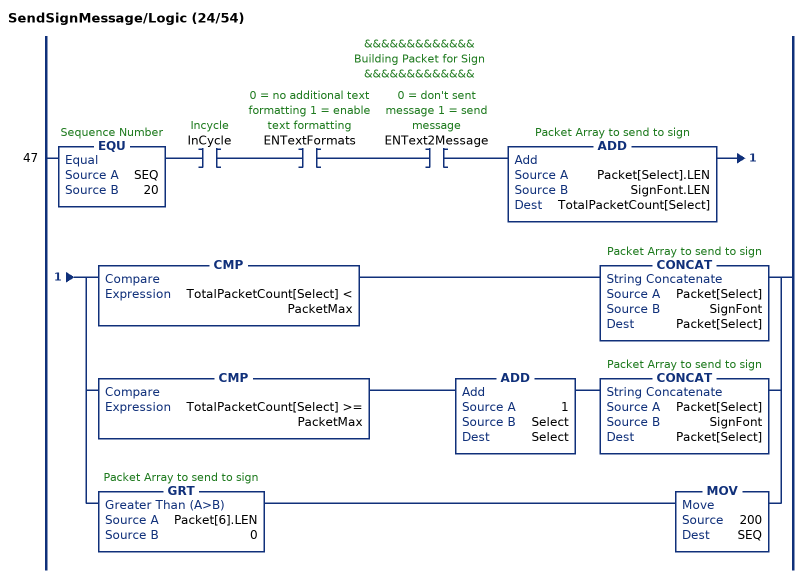
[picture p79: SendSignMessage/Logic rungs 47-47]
   // &&&&&&&&&&&&&
   // Building Packet for Sign
   // &&&&&&&&&&&&&
   47: EQU(SEQ,20)XIC(InCycle)XIC(ENTextFormats)XIC(ENText2Message)ADD(Packet[Select].LEN,SignFont.LEN,TotalPacketCount[Select])[CMP(TotalPacketCount[Select] < PacketMax) CONCAT(Packet[Select],SignFont,Packet[Select]) ,CMP(TotalPacketCount[Select] >= PacketMax) ADD(1,Select,Select) CONCAT(Packet[Select],SignFont,Packet[Select]) ,GRT(Packet[6].LEN,0) MOV(200,SEQ) ];
